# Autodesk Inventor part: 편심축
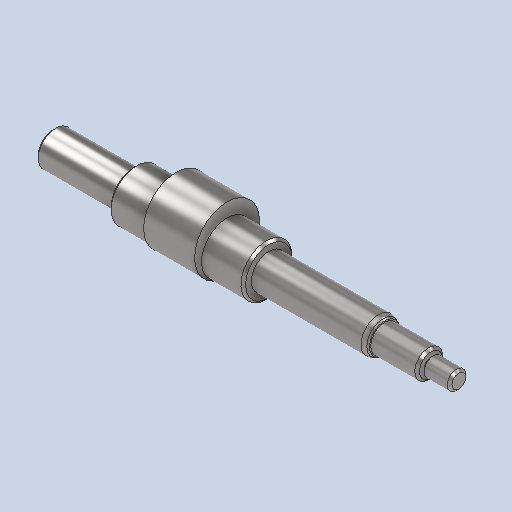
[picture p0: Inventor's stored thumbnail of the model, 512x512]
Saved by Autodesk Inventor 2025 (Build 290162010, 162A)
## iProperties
Created: 2024-07
Part Number: 편심축
Material: 강철, 연강
Document SubType Name: Modeling
Designer: Admin
Density: 7.86 g/cm^3
Appearance: 기본값
Author: jhkim
Sending System: Autodesk Inventor 2025
Preprocessor: ST-DEVELOPER v20
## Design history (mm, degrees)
feature "솔리드1"
node "솔리드2"
